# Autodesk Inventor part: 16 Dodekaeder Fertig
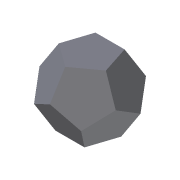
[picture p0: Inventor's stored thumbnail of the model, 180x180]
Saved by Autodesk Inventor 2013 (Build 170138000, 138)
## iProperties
Created: 2012-10
Part Number: 16 Dodekaeder Fertig
Material: Allgemein
Vendor: www.inventor-faq.de
Document SubType Name: Modeling
Designer: Administrator
Manufacturer: www.inventor-faq.de
Density: 1 g/cm^3
RuleStatus: InUse
AfterDocOpen0: inventorfaq
BeforeDocSave0: inventorfaq
Author: Administrator
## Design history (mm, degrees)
derived "16 Dodekaeder.iam"
node "16 Dodekaeder.ipt:1"
node "Fläche1"
node "16 Dodekaeder.ipt:2"
node "16 Dodekaeder.ipt:3"
node "16 Dodekaeder.ipt:4"
node "16 Dodekaeder.ipt:5"
node "16 Dodekaeder.ipt:6"
node "16 Dodekaeder.ipt:7"
node "16 Dodekaeder.ipt:8"
node "16 Dodekaeder.ipt:9"
node "16 Dodekaeder.ipt:10"
node "16 Dodekaeder.ipt:11"
node "16 Dodekaeder.ipt:12"
node "16 Dodekaeder.iam_Körper"
feature "Fläche1::Abgeleitet"
feature "Fläche1::Abgeleitet_1"
feature "Fläche1::Abgeleitet_2"
feature "Fläche1::Abgeleitet_3"
feature "Fläche1::Abgeleitet_4"
feature "Fläche1::Abgeleitet_5"
feature "Fläche1::Abgeleitet_6"
feature "Fläche1::Abgeleitet_7"
feature "Fläche1::Abgeleitet_8"
feature "Fläche1::Abgeleitet_9"
feature "Fläche1::Abgeleitet_10"
feature "Fläche1::Abgeleitet_11"
